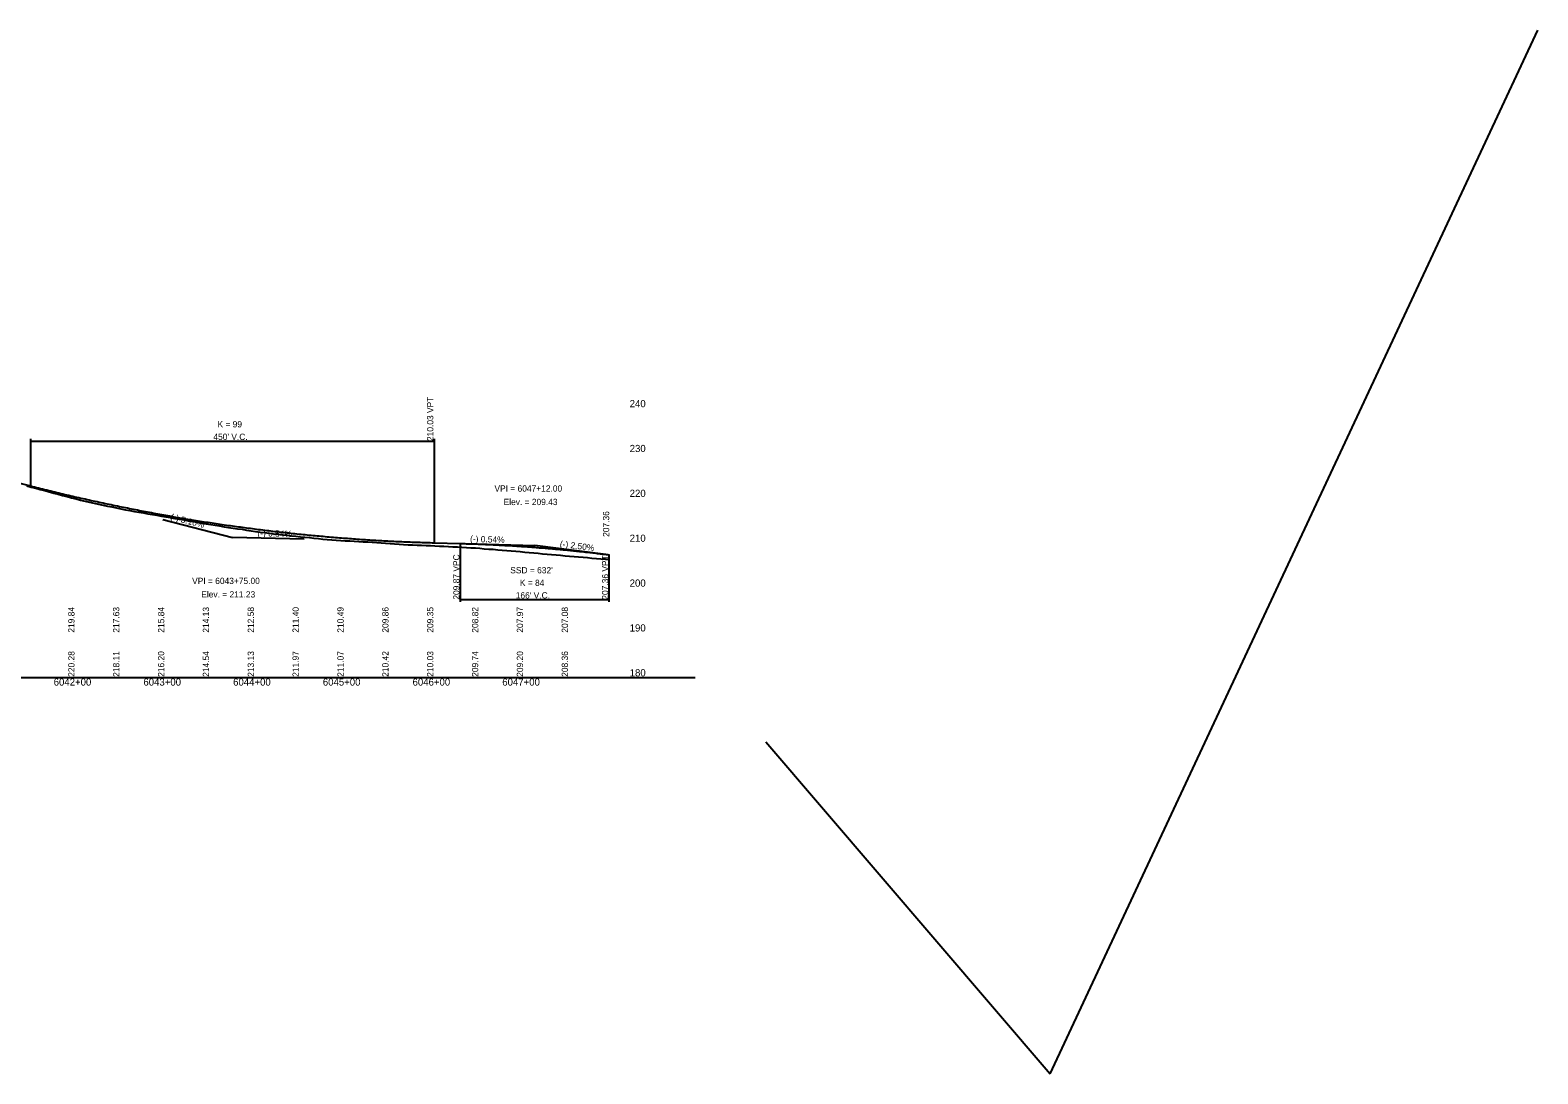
# Model space of a CAD drawing. Extents: x 1876258 to 1932803, y 754739 to 837911.
# Drawn here: x 1915303 to 1916983, y 782747 to 783911 of the extents above; entities that cross this region are included whole.
import ezdxf

# ---------------------------------------------------------------- set-up
doc = ezdxf.new("R2010")
doc.units = 0
for name, color, linetype in [('RD_DDB_ElevTX', 7, 'Continuous'), ('RD_DDB_GradeTX', 7, 'Continuous'), ('RD_DDB_Profile_EX', 7, 'Continuous'), ('RD_DDB_Profile_Lbl', 7, 'Continuous'), ('RD_DDB_Profile_PR', 7, 'Continuous'), ('RD_DDB_StaTX', 7, 'Continuous'), ('RD_DDB_StripGrade', 7, 'Continuous'), ('RD_DDB_VCLbl', 7, 'Continuous'), ('RD_GPK_Profile_Cell', 7, 'Continuous'), ('RD_Sketch8', 7, 'Continuous')]:
    doc.layers.add(name, color=color, linetype=linetype)

msp = doc.modelspace()

# ---------------------------------------------------------------- linework, layer by layer
at = {"layer": 'RD_DDB_GradeTX'}
for p, q in [((1915450.7, 783365.1), (1915528.2, 783345.3)), ((1915608.2, 783343.2), (1915528.2, 783345.3)), ((1915785.3, 783338.4), (1915865.2, 783336.3)), ((1915944.6, 783326.4), (1915865.2, 783336.3))]:
    msp.add_line(p, q, dxfattribs=at)
at = {"layer": 'RD_DDB_Profile_EX'}
for points in [[(1915299, 783402.9), (1915304, 783401.4), (1915309, 783400.2), (1915314, 783398.8), (1915319, 783397.5), (1915324, 783396.1), (1915329, 783394.7), (1915334, 783393.5), (1915339, 783392.1), (1915344, 783390.8), (1915349, 783389.5), (1915354, 783388.2), (1915359, 783386.9), (1915364, 783385.7), (1915369, 783384.5), (1915374, 783383.4), (1915379, 783382.3), (1915384, 783381.3), (1915389, 783380.2), (1915394, 783379.2), (1915399, 783378.1), (1915404, 783377.1), (1915409, 783376.1), (1915414, 783375.2), (1915419, 783374.3), (1915424, 783373.4), (1915429, 783372.6), (1915434, 783371.7), (1915439, 783370.9), (1915444, 783370), (1915449, 783369.1), (1915454, 783368.2), (1915459, 783367.3), (1915464, 783366.5), (1915469, 783365.6), (1915474, 783364.8), (1915479, 783363.9), (1915484, 783363), (1915489, 783362.2), (1915494, 783361.3), (1915499, 783360.5), (1915504, 783359.7), (1915509, 783358.9), (1915514, 783358), (1915519, 783357.2), (1915524, 783356.4), (1915529, 783355.7), (1915534, 783355), (1915539, 783354.3), (1915544, 783353.5)], [(1915299, 783402.9), (1915304, 783401.4), (1915309, 783400.2), (1915314, 783398.8), (1915319, 783397.5), (1915324, 783396.1), (1915329, 783394.7), (1915334, 783393.5), (1915339, 783392.1), (1915344, 783390.8), (1915349, 783389.5), (1915354, 783388.2), (1915359, 783386.9), (1915364, 783385.7), (1915369, 783384.5), (1915374, 783383.4), (1915379, 783382.3), (1915384, 783381.3), (1915389, 783380.2), (1915394, 783379.2), (1915399, 783378.1), (1915404, 783377.1), (1915409, 783376.1), (1915414, 783375.2), (1915419, 783374.3), (1915424, 783373.4), (1915429, 783372.6), (1915434, 783371.7), (1915439, 783370.9), (1915444, 783370), (1915449, 783369.1), (1915454, 783368.2), (1915459, 783367.3), (1915464, 783366.5), (1915469, 783365.6), (1915474, 783364.8), (1915479, 783363.9), (1915484, 783363), (1915489, 783362.2), (1915494, 783361.3), (1915499, 783360.5), (1915504, 783359.7), (1915509, 783358.9), (1915514, 783358), (1915519, 783357.2), (1915524, 783356.4), (1915529, 783355.7), (1915534, 783355), (1915539, 783354.3), (1915544, 783353.5)], [(1915544, 783353.5), (1915549, 783352.7), (1915554, 783351.9), (1915559, 783351.3), (1915564, 783350.6), (1915569, 783349.9), (1915574, 783349.3), (1915579, 783348.8), (1915584, 783348.2), (1915589, 783347.6), (1915594, 783347), (1915599, 783346.5), (1915604, 783346.1), (1915609, 783345.6), (1915614, 783345), (1915619, 783344.5), (1915624, 783343.9), (1915629, 783343.4), (1915634, 783342.9), (1915639, 783342.4), (1915644, 783342.1), (1915649, 783341.8), (1915654, 783341.6), (1915659, 783341.3), (1915664, 783341), (1915669, 783340.7), (1915674, 783340.5), (1915679, 783340.2), (1915684, 783339.8), (1915689, 783339.5), (1915694, 783339.1), (1915699, 783338.7), (1915704, 783338.4), (1915709, 783338.1), (1915714, 783337.8), (1915719, 783337.5), (1915724, 783337.1), (1915729, 783337), (1915734, 783336.7), (1915739, 783336.5), (1915744, 783336.3), (1915749, 783336.1), (1915754, 783335.8), (1915759, 783335.6), (1915764, 783335.4), (1915769, 783335.2), (1915774, 783334.9), (1915779, 783334.7), (1915784, 783334.5), (1915789, 783334.2), (1915794, 783333.8), (1915799, 783333.5), (1915804, 783333.2), (1915809, 783332.7), (1915814, 783332.3), (1915819, 783332), (1915824, 783331.6), (1915829, 783331.1), (1915834, 783330.7), (1915839, 783330.2), (1915844, 783329.8), (1915849, 783329.4), (1915854, 783328.9), (1915859, 783328.5), (1915864, 783328), (1915869, 783327.6), (1915874, 783327.1), (1915879, 783326.7), (1915884, 783326.3), (1915889, 783325.9), (1915894, 783325.4), (1915899, 783324.9), (1915904, 783324.4), (1915909, 783324), (1915914, 783323.6), (1915919, 783323.2), (1915924, 783322.7), (1915929, 783322.3), (1915934, 783321.8), (1915939, 783321.3), (1915944, 783320.9), (1915948.2, 783320.6)], [(1915544, 783353.5), (1915549, 783352.7), (1915554, 783351.9), (1915559, 783351.3), (1915564, 783350.6), (1915569, 783349.9), (1915574, 783349.3), (1915579, 783348.8), (1915584, 783348.2), (1915589, 783347.6), (1915594, 783347), (1915599, 783346.5), (1915604, 783346.1), (1915609, 783345.6), (1915614, 783345), (1915619, 783344.5), (1915624, 783343.9), (1915629, 783343.4), (1915634, 783342.9), (1915639, 783342.4), (1915644, 783342.1), (1915649, 783341.8), (1915654, 783341.6), (1915659, 783341.3), (1915664, 783341), (1915669, 783340.7), (1915674, 783340.5), (1915679, 783340.2), (1915684, 783339.8), (1915689, 783339.5), (1915694, 783339.1), (1915699, 783338.7), (1915704, 783338.4), (1915709, 783338.1), (1915714, 783337.8), (1915719, 783337.5), (1915724, 783337.1), (1915729, 783337), (1915734, 783336.7), (1915739, 783336.5), (1915744, 783336.3), (1915749, 783336.1), (1915754, 783335.8), (1915759, 783335.6), (1915764, 783335.4), (1915769, 783335.2), (1915774, 783334.9), (1915779, 783334.7), (1915784, 783334.5), (1915789, 783334.2), (1915794, 783333.8), (1915799, 783333.5), (1915804, 783333.2), (1915809, 783332.7), (1915814, 783332.3), (1915819, 783332), (1915824, 783331.6), (1915829, 783331.1), (1915834, 783330.7), (1915839, 783330.2), (1915844, 783329.8), (1915849, 783329.4), (1915854, 783328.9), (1915859, 783328.5), (1915864, 783328), (1915869, 783327.6), (1915874, 783327.1), (1915879, 783326.7), (1915884, 783326.3), (1915889, 783325.9), (1915894, 783325.4), (1915899, 783324.9), (1915904, 783324.4), (1915909, 783324), (1915914, 783323.6), (1915919, 783323.2), (1915924, 783322.7), (1915929, 783322.3), (1915934, 783321.8), (1915939, 783321.3), (1915944, 783320.9), (1915948.2, 783320.6)]]:
    msp.add_lwpolyline(points, dxfattribs=at)
at = {"layer": 'RD_DDB_Profile_PR'}
for p, q in [((1915138.2, 783444.7), (1915303.2, 783402.7)), ((1915753.2, 783339.3), (1915782.3, 783338.5))]:
    msp.add_line(p, q, dxfattribs=at)
for points in [[(1915303.2, 783402.7), (1915312.2, 783400.4), (1915321.2, 783398.2), (1915330.2, 783396), (1915339.2, 783393.8), (1915348.2, 783391.7), (1915357.2, 783389.6), (1915366.2, 783387.6), (1915375.2, 783385.6), (1915384.2, 783383.7), (1915393.2, 783381.8), (1915402.2, 783379.9), (1915411.2, 783378.1), (1915420.2, 783376.3), (1915429.2, 783374.6), (1915438.2, 783372.9), (1915447.2, 783371.2), (1915456.2, 783369.6), (1915465.2, 783368), (1915474.2, 783366.5), (1915483.2, 783365), (1915492.2, 783363.5), (1915501.2, 783362.1), (1915510.2, 783360.8), (1915519.2, 783359.4), (1915528.2, 783358.1), (1915537.2, 783356.9), (1915546.2, 783355.7), (1915555.2, 783354.5), (1915564.2, 783353.4), (1915573.2, 783352.3), (1915582.2, 783351.3), (1915591.2, 783350.3), (1915600.2, 783349.3), (1915609.2, 783348.4), (1915618.2, 783347.5), (1915627.2, 783346.7), (1915636.2, 783345.9), (1915645.2, 783345.1), (1915654.2, 783344.4), (1915663.2, 783343.8), (1915672.2, 783343.1), (1915681.2, 783342.5), (1915690.2, 783342), (1915699.2, 783341.5), (1915708.2, 783341), (1915717.2, 783340.6), (1915726.2, 783340.2), (1915735.2, 783339.9), (1915744.2, 783339.6), (1915753.2, 783339.3)], [(1915782.3, 783338.5), (1915785.6, 783338.4), (1915788.9, 783338.3), (1915792.2, 783338.2), (1915795.6, 783338.1), (1915798.9, 783338), (1915802.2, 783337.9), (1915805.5, 783337.7), (1915808.8, 783337.6), (1915812.1, 783337.4), (1915815.5, 783337.3), (1915818.8, 783337.1), (1915822.1, 783337), (1915825.4, 783336.8), (1915828.7, 783336.6), (1915832, 783336.4), (1915835.4, 783336.3), (1915838.7, 783336.1), (1915842, 783335.9), (1915845.3, 783335.6), (1915848.6, 783335.4), (1915852, 783335.2), (1915855.3, 783335), (1915858.6, 783334.7), (1915861.9, 783334.5), (1915865.2, 783334.3), (1915868.5, 783334), (1915871.9, 783333.7), (1915875.2, 783333.5), (1915878.5, 783333.2), (1915881.8, 783332.9), (1915885.1, 783332.6), (1915888.5, 783332.3), (1915891.8, 783332), (1915895.1, 783331.7), (1915898.4, 783331.4), (1915901.7, 783331.1), (1915905, 783330.8), (1915908.4, 783330.4), (1915911.7, 783330.1), (1915915, 783329.7), (1915918.3, 783329.4), (1915921.6, 783329), (1915925, 783328.7), (1915928.3, 783328.3), (1915931.6, 783327.9), (1915934.9, 783327.5), (1915938.2, 783327.1), (1915941.5, 783326.7), (1915944.9, 783326.3), (1915948.2, 783325.9)]]:
    msp.add_spline(points, degree=3, dxfattribs=at)
at = {"layer": 'RD_DDB_VCLbl'}
for p, q in [((1915303.2, 783455.2), (1915303.2, 783402.7)), ((1915303.2, 783452.7), (1915753.2, 783452.7)), ((1915753.2, 783455.2), (1915753.2, 783339.3)), ((1915782.3, 783273.4), (1915782.3, 783338.5)), ((1915948.2, 783273.4), (1915948.2, 783325.9)), ((1915782.3, 783275.9), (1915948.2, 783275.9))]:
    msp.add_line(p, q, dxfattribs=at)
at = {"layer": 'RD_GPK_Profile_Cell'}
msp.add_line((1914544, 783189.1), (1916044, 783189.1), dxfattribs=at)
at = {"layer": 'RD_Sketch8'}
for p, q in [((1916439.7, 782747.4), (1916983.2, 783910.7)), ((1916122.6, 783117.5), (1916439.7, 782747.4))]:
    msp.add_line(p, q, dxfattribs=at)

# ---------------------------------------------------------------- texts
at = {"layer": 'RD_DDB_ElevTX'}
for s, p in [('240', (1915971, 783490.4)), ('230', (1915971, 783440.4)), ('220', (1915971, 783390.4)), ('210', (1915971, 783340.4)), ('200', (1915971, 783290.4)), ('190', (1915971, 783240.4)), ('180', (1915971, 783190.4))]:
    msp.add_text(s, height=8, dxfattribs=at).set_placement(p)
at = {"layer": 'RD_DDB_GradeTX'}
for s, rotation, p in [('(-) 5.10%', 345.6997, (1915458.6, 783365.1)), ('(-) 0.54%', 358.4661, (1915556, 783346.6)), ('(-) 0.54%', 358.4661, (1915793, 783340.2)), ('(-) 2.50%', 352.8766, (1915892.9, 783334.8))]:
    msp.add_text(s, height=7, rotation=rotation, dxfattribs=at).set_placement(p)
at = {"layer": 'RD_DDB_Profile_Lbl'}
for s, p in [('VPI = 6047+12.00', (1915820.3, 783396.3)), ('Elev. = 209.43', (1915830.5, 783381.3)), ('VPI = 6043+75.00', (1915483.3, 783293.3)), ('Elev. = 211.23', (1915493.5, 783278.3))]:
    msp.add_text(s, height=7, dxfattribs=at).set_placement(p)
msp.add_text('207.36', height=7, rotation=90, dxfattribs=at).set_placement((1915948.2, 783345.9))
at = {"layer": 'RD_DDB_StaTX'}
for s, p in [('6042+00', (1915329, 783180.1)), ('6043+00', (1915429, 783180.1)), ('6044+00', (1915529, 783180.1)), ('6045+00', (1915629, 783180.1)), ('6046+00', (1915729, 783180.1)), ('6047+00', (1915829, 783180.1))]:
    msp.add_text(s, height=8, dxfattribs=at).set_placement(p)
at = {"layer": 'RD_DDB_StripGrade'}
for s, p in [('210.03 VPT', (1915752.2, 783452.7)), ('209.87 VPC', (1915781.3, 783275.9)), ('207.36 VPT', (1915947.2, 783275.9)), ('219.84', (1915352.2, 783239.1)), ('217.63', (1915402.2, 783239.1)), ('215.84', (1915452.2, 783239.1)), ('214.13', (1915502.2, 783239.1)), ('212.58', (1915552.2, 783239.1)), ('211.40', (1915602.2, 783239.1)), ('210.49', (1915652.2, 783239.1)), ('209.86', (1915702.2, 783239.1)), ('209.35', (1915752.2, 783239.1)), ('208.82', (1915802.2, 783239.1)), ('207.97', (1915852.2, 783239.1)), ('207.08', (1915902.2, 783239.1)), ('220.28', (1915352.2, 783189.9)), ('218.11', (1915402.2, 783189.9)), ('216.20', (1915452.2, 783189.9)), ('214.54', (1915502.2, 783189.9)), ('213.13', (1915552.2, 783189.9)), ('211.97', (1915602.2, 783189.9)), ('211.07', (1915652.2, 783189.9)), ('210.42', (1915702.2, 783189.9)), ('210.03', (1915752.2, 783189.9)), ('209.74', (1915802.2, 783189.9)), ('209.20', (1915852.2, 783189.9)), ('208.36', (1915902.2, 783189.9))]:
    msp.add_text(s, height=7, rotation=90, dxfattribs=at).set_placement(p)
at = {"layer": 'RD_DDB_VCLbl'}
for s, p in [('K = 99', (1915511.6, 783467.9)), ("450' V.C.", (1915507, 783453.9)), ("SSD = 632'", (1915837.9, 783305.2)), ('K = 84', (1915848.6, 783291.2)), ("166' V.C.", (1915844, 783277.2))]:
    msp.add_text(s, height=7, dxfattribs=at).set_placement(p)

doc.saveas('drawing.dxf')
